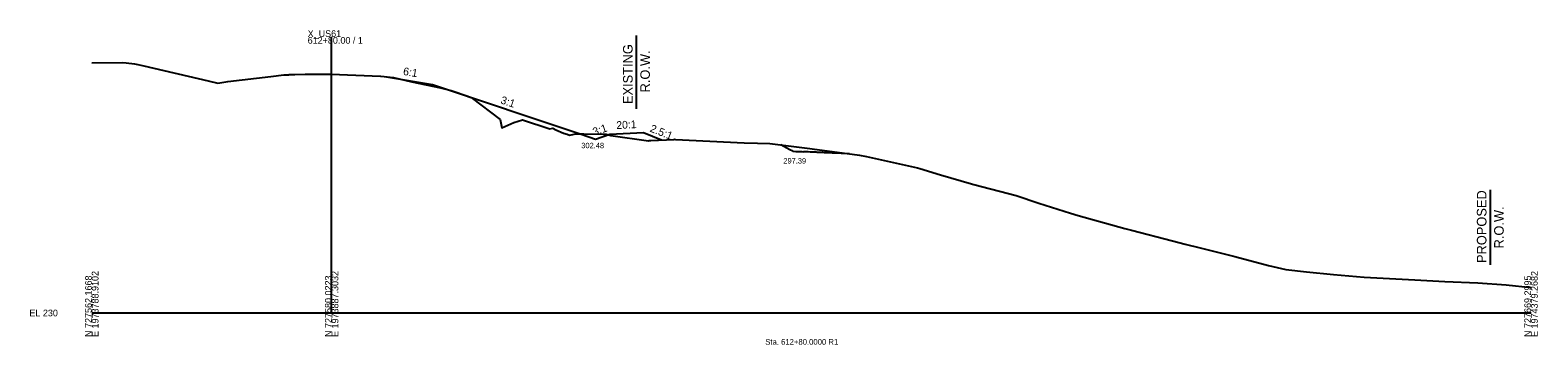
# Model space of a CAD drawing. Extents: x -26 to 1604, y -13 to 9623.
# Drawn here: x -26 to 603, y 1987 to 2118 of the extents above; entities that cross this region are included whole.
import ezdxf

# ---------------------------------------------------------------- set-up
doc = ezdxf.new("R2010")
doc.units = 0
for name, color, linetype in [('Default', 7, 'Continuous'), ('Draft_XS_Grid', 7, 'Continuous'), ('Draft_XS_Text', 7, 'Continuous'), ('DTM CONTOURS_MAJOR', 7, 'Continuous'), ('DTM_X_GROUND', 7, 'Continuous'), ('SLOPE_STAKES_FILL', 7, 'Continuous'), ('XS_CELL', 7, 'Continuous'), ('XS_P_GROUND', 7, 'Continuous'), ('XS_P_ROW', 7, 'Continuous'), ('XS_P_TX_DCH', 7, 'Continuous'), ('XS_P_TX_FS_BS', 7, 'Continuous'), ('XS_X_ROW', 7, 'Continuous')]:
    doc.layers.add(name, color=color, linetype=linetype)

msp = doc.modelspace()

# ---------------------------------------------------------------- linework, layer by layer
at = {"layer": 'DTM_X_GROUND'}
msp.add_lwpolyline([(0, 2104.28), (12.84, 2104.3), (14.28, 2104.17), (17.82, 2103.85), (19.25, 2103.55), (21.68, 2102.91), (48.51, 2096.67), (52.48, 2095.81), (56.78, 2096.46), (74.61, 2098.53), (80.03, 2099.2), (82.03, 2099.29), (82.27, 2099.31), (84.7, 2099.42), (88.91, 2099.44), (99.79, 2099.5), (120.35, 2098.63), (120.46, 2098.62), (120.52, 2098.62), (125.73, 2098.14), (133.49, 2096.29), (145.32, 2093.79), (149.8, 2092.66), (156.76, 2090.29), (156.9, 2090.24), (158.2, 2089.76), (170.29, 2080.59), (170.93, 2077.15), (176, 2079.3), (179.59, 2080.51), (190.91, 2076.72), (192.18, 2077.05), (193.46, 2076.35), (196.72, 2074.86), (198.15, 2074.48), (199.19, 2074.11), (200.58, 2074.43), (201.61, 2074.7), (205.09, 2074.69), (213.34, 2074.52), (214.37, 2074.52), (216.41, 2073.97), (232.05, 2071.72), (232.32, 2071.8), (232.63, 2071.85), (233.04, 2071.91), (242.74, 2072.34), (242.77, 2072.35), (242.81, 2072.36), (243.29, 2072.29), (271.92, 2070.87), (277.49, 2070.78), (282.64, 2070.59), (299.39, 2068.49), (300.25, 2068.45), (320.03, 2065.75), (322.98, 2065.25), (344.16, 2060.45), (345.21, 2060.14), (353.88, 2057.61), (366.67, 2053.86), (367.09, 2053.72), (367.74, 2053.51), (385.41, 2048.93), (394.78, 2045.74), (408.08, 2041.57), (411.19, 2040.6), (430.62, 2035.25), (433.51, 2034.51), (450.52, 2029.99), (455.8, 2028.66), (462.04, 2027.08), (476.55, 2023.54), (490.5, 2019.79), (497.75, 2018.14), (506.36, 2017.1), (517.64, 2016.04), (530.48, 2014.98), (551.53, 2013.74), (564.07, 2013.14), (577.78, 2012.55), (589.64, 2011.67), (600, 2010.6)], dxfattribs=at)
at = {"layer": 'XS_CELL'}
for p, q in [((100, 2000), (100, 2115)), ((0, 2000), (100, 2000)), ((100, 2000), (600, 2000))]:
    msp.add_line(p, q, dxfattribs=at)
at = {"layer": 'XS_P_GROUND'}
for points in [[(122, 2098.48), (142, 2095.15)], [(142, 2095.15), (204, 2074.48), (210, 2072.48), (216, 2074.48), (230, 2075.18), (237.57, 2072.15)], [(292.23, 2067.39), (291.02, 2068.04), (289.76, 2068.7), (288.5, 2069.37), (287.31, 2070.01)], [(292.23, 2067.39), (292.28, 2067.39), (293.54, 2067.33), (293.73, 2067.32), (294.8, 2067.27), (296.06, 2067.22), (296.74, 2067.19)], [(315.87, 2066.32), (314.98, 2066.36), (314.95, 2066.36), (313.77, 2066.41), (313.69, 2066.42), (312.56, 2066.47), (312.43, 2066.47), (311.36, 2066.52), (311.17, 2066.53), (310.17, 2066.58), (309.91, 2066.59), (308.98, 2066.63), (308.65, 2066.64), (307.81, 2066.68), (307.39, 2066.7), (306.66, 2066.74), (306.13, 2066.76), (305.52, 2066.79), (304.87, 2066.82), (304.41, 2066.84), (303.61, 2066.87), (303.33, 2066.89), (302.35, 2066.93), (302.3, 2066.93), (302.1, 2066.94), (301.09, 2066.99), (300.95, 2066.99), (299.83, 2067.04), (299.5, 2067.06), (298.58, 2067.1), (298.06, 2067.13), (297.32, 2067.16), (297.02, 2067.17), (296.74, 2067.19)]]:
    msp.add_lwpolyline(points, dxfattribs=at)
at = {"layer": 'XS_P_ROW'}
msp.add_line((583, 2051.27), (583, 2020), dxfattribs=at)
at = {"layer": 'XS_X_ROW'}
msp.add_line((227, 2115.55), (227, 2085), dxfattribs=at)

# ---------------------------------------------------------------- texts
at = {"layer": 'Default'}
for p in [(121.96, 2098.42), (237.53, 2072.09)]:
    msp.add_text('X', height=0.12, dxfattribs=at).set_placement(p)
at = {"layer": 'Draft_XS_Grid'}
msp.add_text('-', height=0.0001, dxfattribs=at).set_placement((0, 2000))
at = {"layer": 'Draft_XS_Text'}
msp.add_text('Sta. 612+80.0000 R1', height=2.4, dxfattribs=at).set_placement((280.75, 1986.75))
at = {"layer": 'DTM CONTOURS_MAJOR'}
for p in [(287.27, 2069.95), (292.19, 2067.33), (292.19, 2067.33), (302.06, 2066.88), (315.83, 2066.26)]:
    msp.add_text('X', height=0.12, dxfattribs=at).set_placement(p)
at = {"layer": 'SLOPE_STAKES_FILL'}
for p in [(141.96, 2095.09), (203.96, 2074.42), (215.96, 2074.42), (229.96, 2075.12), (209.96, 2072.42)]:
    msp.add_text('X', height=0.12, dxfattribs=at).set_placement(p)
at = {"layer": 'XS_CELL'}
for s, p in [('X_US61', (90, 2115)), ('612+80.00 / 1', (90, 2112.2)), ('EL 230', (-26, 1998.6))]:
    msp.add_text(s, height=2.8, dxfattribs=at).set_placement(p)
for s, p in [('N 727562.1668', (0, 1990)), ('E 1973788.9102', (2.8, 1990)), ('N 727580.0223', (100, 1990)), ('E 1973887.3032', (102.8, 1990)), ('N 727669.2995', (600, 1990)), ('E 1974379.2682', (602.8, 1990))]:
    msp.add_text(s, height=2.8, rotation=90, dxfattribs=at).set_placement(p)
at = {"layer": 'XS_P_ROW'}
for s, p in [('PROPOSED', (581.42, 2020.81)), ('R.O.W.', (588.62, 2026.89))]:
    msp.add_text(s, height=4, rotation=90, dxfattribs=at).set_placement(p)
at = {"layer": 'XS_P_TX_DCH'}
for s, p in [('302.48', (204.07, 2068.65)), ('297.39', (288.3, 2062.27))]:
    msp.add_text(s, height=2.25, dxfattribs=at).set_placement(p)
at = {"layer": 'XS_P_TX_FS_BS'}
for s, rotation, p in [('6:1', 350.53766, (129.62, 2099.21)), ('3:1', 341.56507, (170.16, 2087.4)), ('3:1', 18.43493, (209.45, 2073.84)), ('20:1', 2.86241, (218.75, 2076.62)), ('2.5:1', 338.19859, (232.42, 2075.67))]:
    msp.add_text(s, height=3.24, rotation=rotation, dxfattribs=at).set_placement(p)
at = {"layer": 'XS_X_ROW'}
for s, p in [('EXISTING', (225.47, 2087.04)), ('R.O.W.', (232.67, 2091.89))]:
    msp.add_text(s, height=4, rotation=90, dxfattribs=at).set_placement(p)

doc.saveas('drawing.dxf')
